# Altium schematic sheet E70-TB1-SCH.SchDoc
size A4
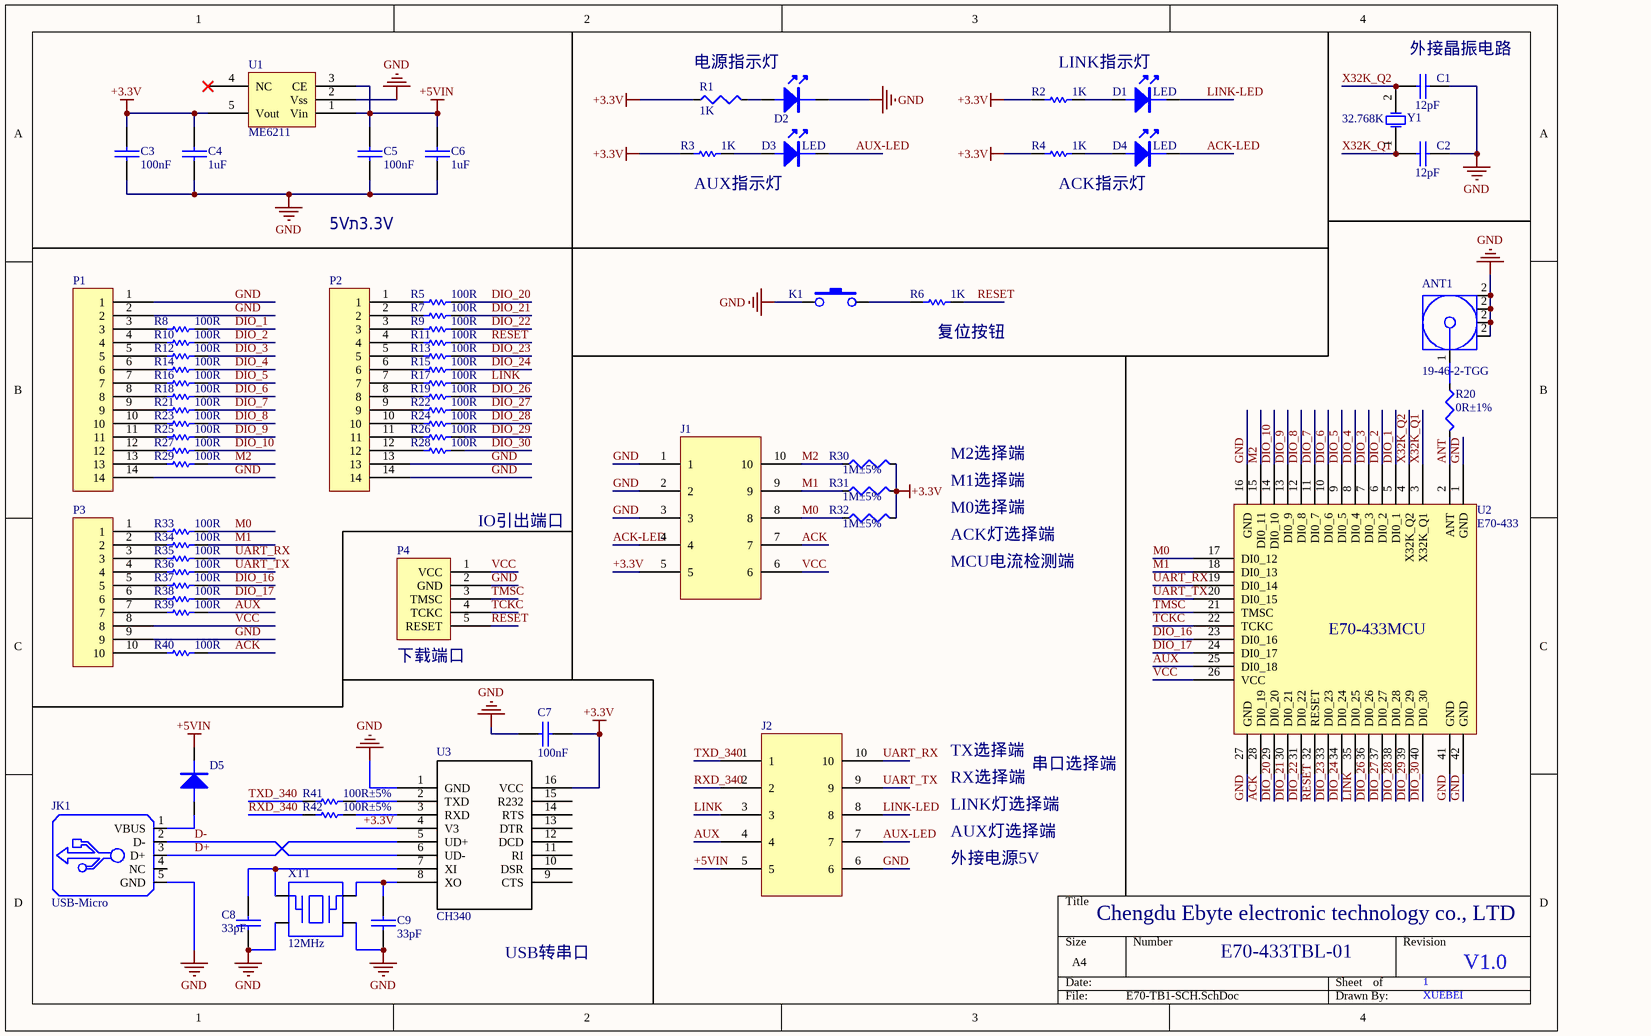
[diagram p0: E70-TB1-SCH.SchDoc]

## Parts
ANT1  19-46-2-TGG  [PCBComponent_1 - duplicate]
C1  12pF  [0402-CAP]
C2  12pF  [0402-CAP]
C3  100nF  [E-CAP-0402]
C4  1uF  [E-CAP-0402]
C5  100nF  [E-CAP-0402]
C6  1uF  [E-CAP-0402]
C7  100nF  [E-CAP-0402]
C8  33pF  [E-CAP-0402]
C9  33pF  [E-CAP-0402]
D1  LED  [E-LED-0603]
D2  LED  [E-LED-0603]  (value not drawn)
D3  LED  [E-LED-0603]
D4  LED  [E-LED-0603]
D5  SOD-123  [E-RES-1206]  (value not drawn)
J1  (no value)  [DIP10]
J2  (no value)  [DIP10]
JK1  USB-Micro  [E-Micro USB-5SB]
K1  KEY0  [PCBComponent_1]  (value not drawn)
P1  (no value)  [14PIN-2.54]
P2  (no value)  [14PIN-2.54]
P3  (no value)  [E-10P-2.54-1]
P4  (no value)  [E-5P-2.54-1]
R1  1K  [E-RES-0402]
R2  1K  [E-RES-0402]
R3  1K  [E-RES-0402]
R4  1K  [E-RES-0402]
R5  100R  [E-RES-0402]
R6  1K  [E-RES-0402]
R7  100R  [E-RES-0402]
R8  100R  [E-RES-0402]
R9  100R  [E-RES-0402]
R10  100R  [E-RES-0402]
R11  100R  [E-RES-0402]
R12  100R  [E-RES-0402]
R13  100R  [E-RES-0402]
R14  100R  [E-RES-0402]
R15  100R  [E-RES-0402]
R16  100R  [E-RES-0402]
R17  100R  [E-RES-0402]
R18  100R  [E-RES-0402]
R19  100R  [E-RES-0402]
R20  0R±1%  [E-RES-0402]
R21  100R  [E-RES-0402]
R22  100R  [E-RES-0402]
R23  100R  [E-RES-0402]
R24  100R  [E-RES-0402]
R25  100R  [E-RES-0402]
R26  100R  [E-RES-0402]
R27  100R  [E-RES-0402]
R28  100R  [E-RES-0402]
R29  100R  [E-RES-0402]
R30  1M±5%  [E-RES-0402]
R31  1M±5%  [E-RES-0402]
R32  1M±5%  [E-RES-0402]
R33  100R  [E-RES-0402]
R34  100R  [E-RES-0402]
R35  100R  [E-RES-0402]
R36  100R  [E-RES-0402]
R37  100R  [E-RES-0402]
R38  100R  [E-RES-0402]
R39  100R  [E-RES-0402]
R40  100R  [E-RES-0402]
R41  100R±5%  [E-RES-0402]
R42  100R±5%  [E-RES-0402]
U1  ME6211  [E-SOT23-5]
U2  E70-433  [E71-433MS20]
U3  CH340  [E-SOP16]
XT1  12MHz  [E-XT3225-4]
Y1  32.768K  [XT2520]

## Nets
+3.3V: C3.1 C4.1 C7.1 J1.5 R1.1 R2.1 R3.1 R4.1 R30.2 R31.2 R32.2 U1.5(Vout) U3.4(V3) U3.16(VCC)
+5VIN: C5.1 C6.1 D5.2 J2.5 U1.1(Vin) U1.3(CE)
GND: ANT1.2(GND) C1.1 C2.1 C3.2 C4.2 C5.2 C6.2 C7.2 C8.1 C9.1 D2.K J1.1 J1.2 J1.3 J2.6 JK1.5(GND) K1.1 P1.1 P1.2 P1.14 P2.13 P2.14 P3.9 P4.2(GND) U1.2(Vss) U2.1(GND) U2.16(GND) U2.27(GND) U2.41(GND) U2.42(GND) U3.1(GND) XT1.3 XT1.4
ACK: J1.7 R40.2 U2.28(DI0_19)
ACK-LED: D4.K J1.4
ANT: R20.2 U2.2(ANT)
AUX: J2.4 R39.2 U2.25(DI0_18)
AUX-LED: D3.K J2.7
D+: JK1.3(D+) U3.5(UD+)
D-: JK1.2(D-) U3.6(UD-)
DIO_1: R8.2 U2.5(DI0_1)
DIO_2: R10.2 U2.6(DI0_2)
DIO_3: R12.2 U2.7(DI0_3)
DIO_4: R14.2 U2.8(DI0_4)
DIO_5: R16.2 U2.9(DI0_5)
DIO_6: R18.2 U2.10(DI0_6)
DIO_7: R21.2 U2.11(DI0_7)
DIO_8: R23.2 U2.12(DI0_8)
DIO_9: R25.2 U2.13(DI0_9)
DIO_10: R27.2 U2.14(DI0_10)
DIO_16: R37.2 U2.23(DI0_16)
DIO_17: R38.2 U2.24(DI0_17)
DIO_20: R5.2 U2.29(DI0_20)
DIO_21: R7.2 U2.30(DI0_21)
DIO_22: R9.2 U2.31(DI0_22)
DIO_23: R13.2 U2.33(DI0_23)
DIO_24: R15.2 U2.34(DI0_24)
DIO_26: R19.2 U2.36(DI0_26)
DIO_27: R22.2 U2.37(DI0_27)
DIO_28: R24.2 U2.38(DI0_28)
DIO_29: R26.2 U2.39(DI0_29)
DIO_30: R28.2 U2.40(DI0_30)
LINK: J2.3 R17.2 U2.35(DI0_25)
LINK-LED: D1.K J2.8
M0: J1.8 R32.1 R33.2 U2.17(DI0_12)
M1: J1.9 R31.1 R34.2 U2.18(DI0_13)
M2: J1.10 R29.2 R30.1 U2.15(DI0_11)
RESET: P4.5(RESET) R6.2 R11.2 U2.32(RESET)
RXD_340: J2.2 R42.1
TCKC: P4.4(TCKC) U2.22(TCKC)
TMSC: P4.3(TMSC) U2.21(TMSC)
TXD_340: J2.1 R41.1
UART_RX: J2.10 R35.2 U2.19(DI0_14)
UART_TX: J2.9 R36.2 U2.20(DI0_15)
VCC: J1.6 P3.8 P4.1(VCC) U2.26(VCC)
X32K_Q1: C2.2 U2.3(X32K_Q1) Y1.1(OSC1)
X32K_Q2: C1.2 U2.4(X32K_Q2) Y1.2(OSC2)
NetANT1_1: ANT1.1(Signal) R20.1
NetC8_2: C8.2 U3.7(XI) XT1.1
NetC9_2: C9.2 U3.8(XO) XT1.2
NetD1_A: D1.A R2.2
NetD2_A: D2.A R1.2
NetD3_A: D3.A R3.2
NetD4_A: D4.A R4.2
NetD5_1: D5.1 JK1.1(VBUS)
NetK1_2: K1.2 R6.1
NetP1_3: P1.3 R8.1
NetP1_4: P1.4 R10.1
NetP1_5: P1.5 R12.1
NetP1_6: P1.6 R14.1
NetP1_7: P1.7 R16.1
NetP1_8: P1.8 R18.1
NetP1_9: P1.9 R21.1
NetP1_10: P1.10 R23.1
NetP1_11: P1.11 R25.1
NetP1_12: P1.12 R27.1
NetP1_13: P1.13 R29.1
NetP2_1: P2.1 R5.1
NetP2_2: P2.2 R7.1
NetP2_3: P2.3 R9.1
NetP2_4: P2.4 R11.1
NetP2_5: P2.5 R13.1
NetP2_6: P2.6 R15.1
NetP2_7: P2.7 R17.1
NetP2_8: P2.8 R19.1
NetP2_9: P2.9 R22.1
NetP2_10: P2.10 R24.1
NetP2_11: P2.11 R26.1
NetP2_12: P2.12 R28.1
NetP3_1: P3.1 R33.1
NetP3_2: P3.2 R34.1
NetP3_3: P3.3 R35.1
NetP3_4: P3.4 R36.1
NetP3_5: P3.5 R37.1
NetP3_6: P3.6 R38.1
NetP3_7: P3.7 R39.1
NetP3_10: P3.10 R40.1
NetR41_2: R41.2 U3.2(TXD)
NetR42_2: R42.2 U3.3(RXD)

Not connected (* = marked no-connect by the designer): JK1 4(NC); U1 4(NC)*; U3 9(CTS) 10(DSR) 11(RI) 12(DCD) 13(DTR) 14(RTS) 15(R232)

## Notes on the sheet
- (near R1) 电源指示灯
- LINK指示灯
- (near C1) 外接晶振电路
- 5Vת3.3V
- (near R3) AUX指示灯
- ACK指示灯
- (near R6) 复位按钮
- M0选择端
- M1选择端
- M2选择端
- IO引出端口
- MCU电流检测端
- ACK灯选择端
- (near P4) 下载端口
- TX选择端
- RX选择端
- 串口选择端
- AUX灯选择端
- LINK灯选择端
- 外接电源5V
- Chengdu Ebyte electronic technology co., LTD
- USB转串口
- E70-433TBL-01
- 1
- V1.0
- XUEBEI

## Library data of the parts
ANT1 = 19-46-2-TGG: SMA RF Coaxial PCB Connector, SM, Vertical Mount Socket, 50 Ohm Impedance
C1 C2 = cap0402: Capacitor
C3-C6 = cap0603: Capacitor
C7-C9 = CAP: Capacitor
D5 = DIODE
J1 J2 = 2X5-2.54
JK1 = USB-MINI
P1 P2 = 14PIN-2.54
P3 = 10PIN-2.54
P4 = E70-DOWNLOAD
R1 R20 R30-R32 = res0603
R2-R19 R21-R29 R33-R42 = RES1
U3 = CH340G
XT1 = XT-SMD1
Y1 = XTAL: Crystal Oscillator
